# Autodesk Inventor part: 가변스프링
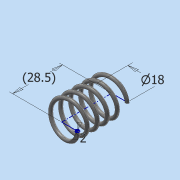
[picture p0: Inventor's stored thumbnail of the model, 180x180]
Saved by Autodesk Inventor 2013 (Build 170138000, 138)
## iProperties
Created: 2018-12
Part Number: 가변스프링
Material: 스테인레스 스틸
Document SubType Name: Modeling
Designer: dgall
Density: 8.08 g/cm^3
Mass: 7.05664 g
Surface Area: 17.7435 cm^2
Volume: 0.873347 cm^3
Author: dgall
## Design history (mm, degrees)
sketch "스케치1"
  geometry: L1 (0, 0)-(9, 0); L2 (0, 0)-(0, 28.5); L3 (0, 28.5)-(9, 28.5); C1 r 1 at (9, 0)
  constraints: 6 end point, 1 centre point, 1 coincident, 1 horizontal, 1 perpendicular, 1 vertical, 1 vertical alignment
  dimensions: "d0" = 18 diameter of L3.end L2; "d2" = 28.5 distance of L1.start L2.end (derived); "d3" = 2 diameter of C1
feature "코일1" pitch "d4" = 10; turns "d6" = 5; dims "d5" = 28.5 (= d2), "d7" = 0, angle "d8" = 90 deg, angle "d9" = 90 deg, "d10" = 0, "d11" = 0
node "작업 평면1"
feature "분할1"
feature "분할2"
node "솔리드1"
other parameters: "d12" = 0
